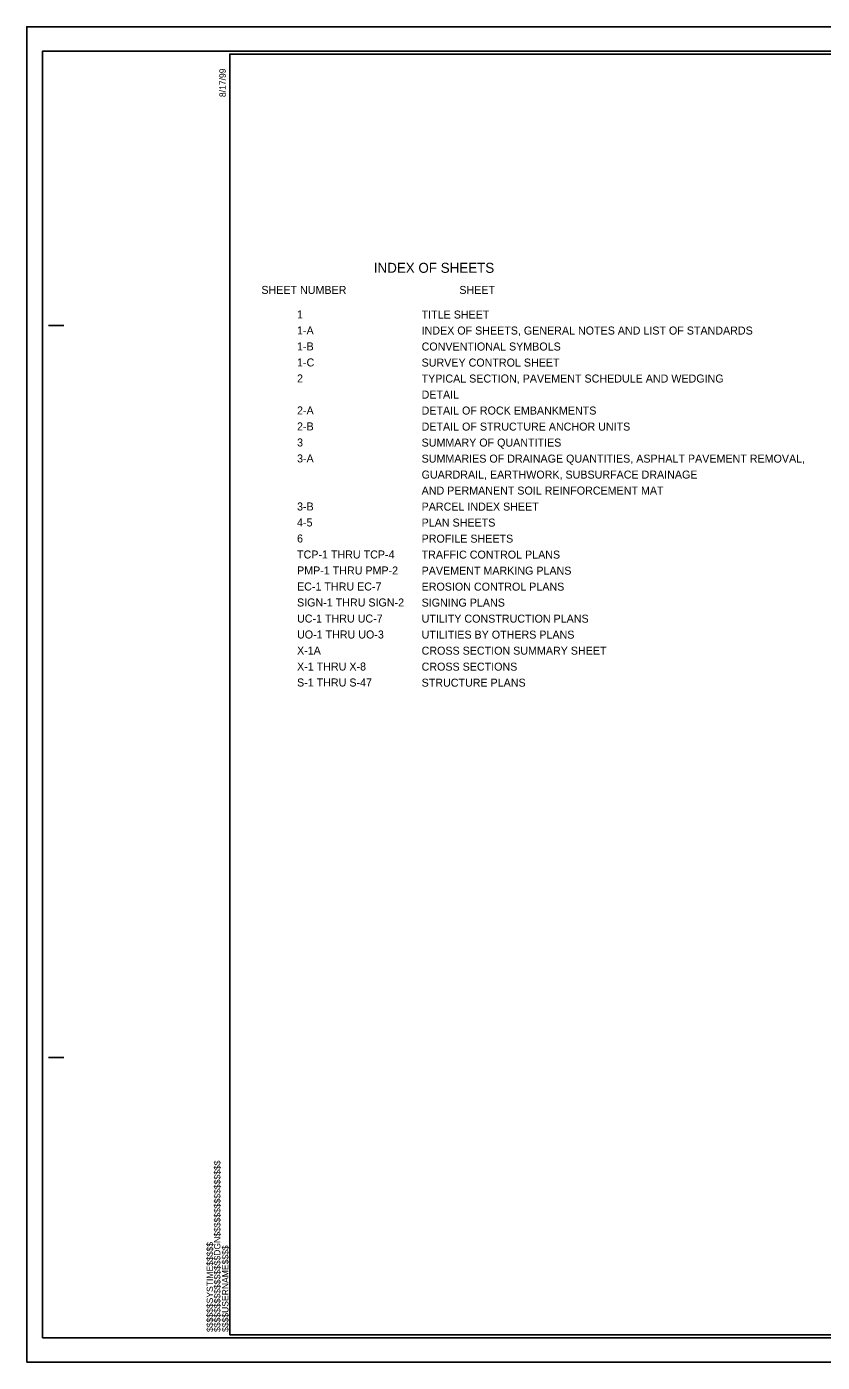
# Model space of a CAD drawing. Extents: x 1729968.4 to 1730002.1, y 539936.7 to 539958.6.
# Drawn here: x 1729968.43 to 1729981.47, y 539936.68 to 539958.58 of the extents above; entities that cross this region are included whole.
import ezdxf

# ---------------------------------------------------------------- set-up
doc = ezdxf.new("R2010")
doc.units = 0
for name, color, linetype in [('Prop RDY Alternate Text Green', 7, 'Continuous'), ('Sheet Cutting Line CELL', 7, 'Continuous'), ('Sheet Plan CELL', 7, 'Continuous'), ('Sheet Plot Border Inside CELL', 7, 'Continuous'), ('Sheet Plot Border Outside CELL', 7, 'Continuous')]:
    doc.layers.add(name, color=color, linetype=linetype)

msp = doc.modelspace()

# ---------------------------------------------------------------- linework, layer by layer
at = {"layer": 'Sheet Cutting Line CELL'}
for p, q in [((1730002.096, 539958.582), (1729968.426, 539958.582)), ((1729968.426, 539958.582), (1729968.426, 539936.682)), ((1729968.426, 539936.682), (1730002.096, 539936.682))]:
    msp.add_line(p, q, dxfattribs=at)
at = {"layer": 'Sheet Plan CELL'}
for p, q in [((1729971.756, 539958.132), (1729971.756, 539958.132)), ((1729968.786, 539953.682), (1729969.036, 539953.682)), ((1729968.786, 539941.682), (1729969.036, 539941.682)), ((1729971.756, 539937.132), (1729971.756, 539937.132))]:
    msp.add_line(p, q, dxfattribs=at)
msp.add_lwpolyline([(1730001.756, 539958.132), (1729971.756, 539958.132), (1729971.756, 539937.132), (1730001.756, 539937.132)], close=True, dxfattribs=at)
at = {"layer": 'Sheet Plot Border Inside CELL'}
msp.add_lwpolyline([(1729968.686, 539937.082), (1730002.006, 539937.082), (1730002.006, 539958.182), (1729968.686, 539958.182)], close=True, dxfattribs=at)
at = {"layer": 'Sheet Plot Border Outside CELL'}
msp.add_lwpolyline([(1729968.426, 539936.682), (1730002.096, 539936.682), (1730002.096, 539958.582), (1729968.426, 539958.582)], close=True, dxfattribs=at)

# ---------------------------------------------------------------- texts
at = {"layer": 'Prop RDY Alternate Text Green'}
for s, height, p in [('INDEX OF SHEETS', 0.16403, (1729974.119, 539954.546)), ('SHEET NUMBER                                      SHEET', 0.13122, (1729972.275, 539954.2)), ('1', 0.131, (1729972.86, 539953.799)), ('TITLE SHEET', 0.13122, (1729974.903, 539953.796)), ('1-A', 0.1312, (1729972.86, 539953.536)), ('INDEX OF SHEETS, GENERAL NOTES AND LIST OF STANDARDS', 0.13122, (1729974.903, 539953.534)), ('1-B', 0.1312, (1729972.86, 539953.274)), ('CONVENTIONAL SYMBOLS', 0.13122, (1729974.903, 539953.272)), ('1-C', 0.1312, (1729972.86, 539953.011)), ('SURVEY CONTROL SHEET', 0.13122, (1729974.903, 539953.009)), ('2', 0.131, (1729972.86, 539952.749)), ('TYPICAL SECTION, PAVEMENT SCHEDULE AND WEDGING', 0.13122, (1729974.903, 539952.747)), ('DETAIL', 0.1312, (1729974.903, 539952.484)), ('2-A', 0.1312, (1729972.86, 539952.224)), ('DETAIL OF ROCK EMBANKMENTS', 0.13122, (1729974.903, 539952.222)), ('2-B', 0.1312, (1729972.86, 539951.962)), ('DETAIL OF STRUCTURE ANCHOR UNITS', 0.13122, (1729974.903, 539951.959)), ('3', 0.131, (1729972.86, 539951.699)), ('SUMMARY OF QUANTITIES', 0.13122, (1729974.903, 539951.697)), ('3-A', 0.1312, (1729972.86, 539951.437)), ('SUMMARIES OF DRAINAGE QUANTITIES, ASPHALT PAVEMENT REMOVAL, ', 0.13122, (1729974.903, 539951.434)), ('GUARDRAIL, EARTHWORK, SUBSURFACE DRAINAGE ', 0.13122, (1729974.903, 539951.172)), ('AND PERMANENT SOIL REINFORCEMENT MAT', 0.13122, (1729974.903, 539950.91)), ('3-B', 0.1312, (1729972.86, 539950.649)), ('PARCEL INDEX SHEET', 0.13122, (1729974.903, 539950.647)), ('4-5', 0.1312, (1729972.86, 539950.387)), ('PLAN SHEETS', 0.13122, (1729974.903, 539950.385)), ('6', 0.131, (1729972.86, 539950.124)), ('PROFILE SHEETS', 0.13122, (1729974.903, 539950.122)), ('TCP-1 THRU TCP-4', 0.13122, (1729972.86, 539949.862)), ('TRAFFIC CONTROL PLANS', 0.13122, (1729974.903, 539949.86)), ('PMP-1 THRU PMP-2', 0.13122, (1729972.86, 539949.6)), ('PAVEMENT MARKING PLANS', 0.13122, (1729974.903, 539949.597)), ('EC-1 THRU EC-7', 0.13122, (1729972.86, 539949.337)), ('EROSION CONTROL PLANS', 0.13122, (1729974.903, 539949.335)), ('SIGN-1 THRU SIGN-2', 0.13122, (1729972.86, 539949.075)), ('SIGNING PLANS', 0.13122, (1729974.903, 539949.073)), ('UC-1 THRU UC-7', 0.13122, (1729972.86, 539948.812)), ('UTILITY CONSTRUCTION PLANS', 0.13122, (1729974.903, 539948.81)), ('UO-1 THRU UO-3', 0.13122, (1729972.86, 539948.55)), ('UTILITIES BY OTHERS PLANS', 0.13122, (1729974.903, 539948.548)), ('X-1A', 0.1312, (1729972.86, 539948.287)), ('CROSS SECTION SUMMARY SHEET', 0.13122, (1729974.903, 539948.285)), ('X-1 THRU X-8', 0.13122, (1729972.86, 539948.025)), ('CROSS SECTIONS', 0.13122, (1729974.903, 539948.023)), ('S-1 THRU S-47', 0.13122, (1729972.86, 539947.763)), ('STRUCTURE PLANS', 0.13122, (1729974.903, 539947.76))]:
    msp.add_text(s, height=height, dxfattribs=at).set_placement(p)
at = {"layer": 'Sheet Plan CELL'}
for s, p in [('8/17/99', (1729971.691, 539957.428)), ('$$$$$$$$$$$$$$$$DGN$$$$$$$$$$$$$$$$', (1729971.603, 539937.179)), ('$$$$$$SYSTIME$$$$$', (1729971.482, 539937.179)), ('$$$$USERNAME$$$$', (1729971.735, 539937.179))]:
    msp.add_text(s, height=0.105, rotation=90, dxfattribs=at).set_placement(p)

doc.saveas('drawing.dxf')
